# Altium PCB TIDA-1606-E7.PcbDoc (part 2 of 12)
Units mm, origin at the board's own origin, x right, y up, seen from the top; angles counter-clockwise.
Board outline 270 x 345 mm, 4 copper layers (Top Layer, Signal Layer 1, Signal Layer 2, Bottom Layer), stack 2.326 mm thick; 1282 components, 576 nets, 3628 pads, 4132 vias.
Unrouted connection lines stored in the file: 1719.
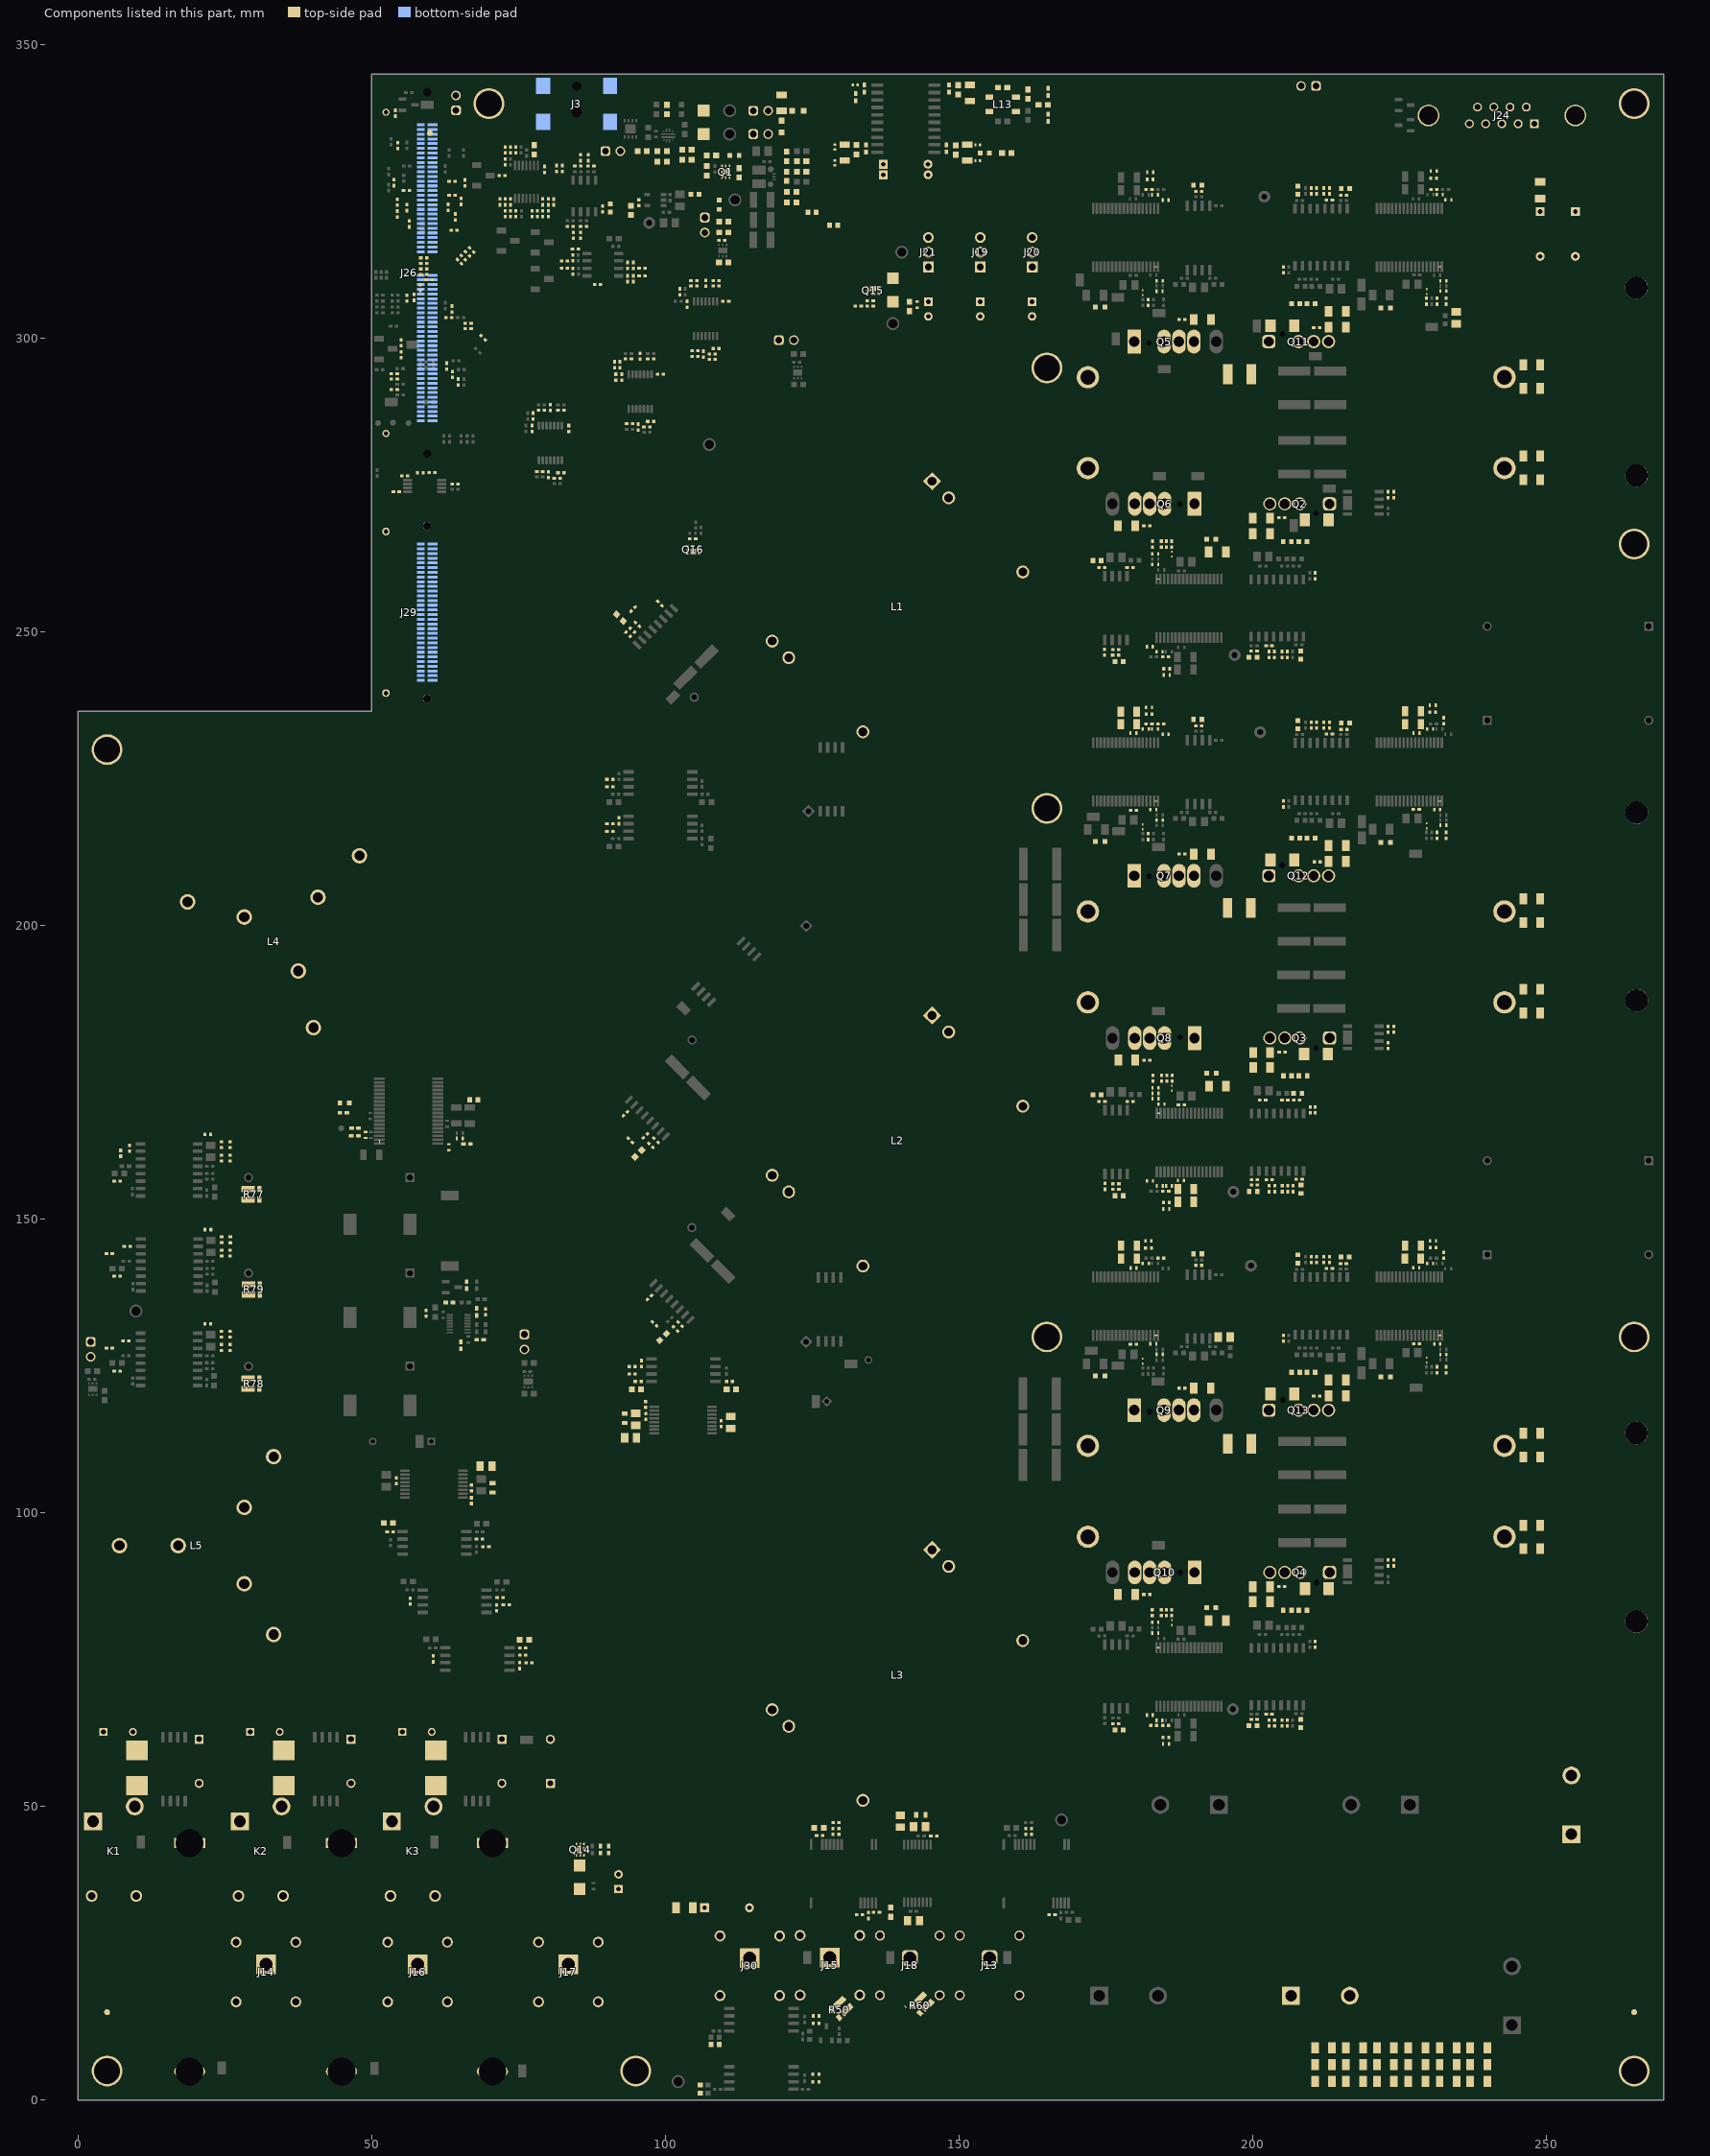
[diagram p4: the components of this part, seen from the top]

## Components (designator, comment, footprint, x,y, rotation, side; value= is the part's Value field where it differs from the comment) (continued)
C301 "GRM1555C1H101JA01D" 0402L 63.727,324.376 r0 top value=100pF
C302 "GRM155R71E104KE14D" 0402L 71.326,83.866 r270 top value=0.1uF
C303 "GRM155R71E104KE14D" 0402L 174.851,246.6 r270 top value=0.1uF
C304 "GCM155R71H104KE02D" 0402L 179.159,261.029 r180 top value=0.1uF
C305 "EMK107BB7225KA-T" 0603 52.884,98.3 r180 top value=2.2uF
C306 "GRM1555C1H101JA01D" 0402L 176.719,247.035 r0 top value=100pF
C307 "GCM155R71H104KE02D" 0402L 174.357,261.029 r180 top value=0.1uF
C308 "GRM155R71E104KE14D" 0402L 53.184,96.83 r0 top value=0.1uF
C309 "EMK107BB7225KA-T" 0603L 173.533,262.198 r0 top value=2.2uF
C310 "GRM1555C1E301JA01D" 0402L 79.511,328.803 r90 top value=300pF
C311 "EMK107BB7225KA-T" 0603 77.734,332.13 r90 top value=2.2uF
C312 "GRM155R71E104KE14D" 0402L 95.288,251.328 r135 top value=0.1uF
C313 "GRM1555C1E751JA01D" 0402L 72.759,323.261 r270 top value=750pF
C314 "GRM155R71E104KE14D" 0402L 95.532,323.12 r270 top value=0.1uF
C315 "GRM155R71E104KE14D" 0402L 223.117,179.6 r270 top value=0.1uF
C316 "GRM1555C1E751JA01D" 0402L 77.362,321.253 r90 top value=750pF
C317 "GRM155R71E104KE14D" 0402L 54.457,332.867 r90 top value=0.1uF
C318 "GRM155R71E104KE14D" 0402L 174.893,155.634 r270 top value=0.1uF
C319 "CL31B106KBHNNNE" 1206_180L 188.657,155.145 r0 top value=10uF
C320 "CL31B106KBHNNNE" 1206_180L 188.66,153 r0 top value=10uF
C321 "GCM155R71H104KE02D" 0402S 187.835,156.642 r0 top value=0.1uF
C322 "GRM155R71E104KE14D" 0402L 75.76,77.056 r180 top value=0.1uF
C323 "EMK107BB7225KA-T" 0603 76.06,78.425 r0 top value=2.2uF
C324 "CGA2B2C0G1H102J050BA" 0402L 56.637,85 r270 top value=1000pF
C325 "GCM155R71H104KE02D" 0402L 187.902,169.5 r0 top value=0.1uF
C326 "GRM1555C1H101JA01D" 0402L 53.802,326.525 r90 top value=100pF
C327 "GRM155R71E104KE14D" 0402L 75.21,74.025 r270 top value=0.1uF
C328 "GRM155R71E104KE14D" 0402L 96.646,164.233 r225 top value=0.1uF
C329 "GRM1555C1E301JA01D" 0402L 63.036,322.342 r90 top value=300pF
C330 "GRM155R71E104KE14D" 0402S 185.808,155.68 r0 top value=0.1uF
C331 "CGA2B2X7R1H331K050BA" 0402S 184.508,169.632 r180 top value=330pF
C332 "CGA2B2X7R1H331K050BA" 0402S 183.492,171.459 r180 top value=330pF
C333 "GRM1555C1H101JA01D" 0402L 200.339,156.753 r180 top value=100pF
C334 "GCM155R71H104KE02D" 0402L 207.518,170.288 r0 top value=0.1uF
C335 "GRM1555C1E751JA01D" 0402L 79.187,323.261 r270 top value=750pF
C336 "EMK107BB7225KA-T" 0603L 207.734,171.484 r180 top value=2.2uF
C337 "GCM155R71H104KE02D" 0402L 201.755,170.288 r180 top value=0.1uF
C338 "GRM155R71E104KE14D" 0402L 207.959,156.853 r0 top value=0.1uF
C339 "GCM155R71H104KE02D" 0402L 205.531,170.292 r0 top value=0.1uF
C340 "GRM1555C1E301JA01D" 0402L 223.117,91.501 r90 top value=300pF
C341 "GRM1555C1H101JA01D" 0402L 206.911,155.232 r270 top value=100pF
C342 "GRM1555C1H102JA01D" 0402L 129.098,47.3 r0 top value=1000pF
C343 "GRM1555C1H101JA01D" 0402L 209.839,168.632 r270 top value=100pF
C344 "GRM1555C1E301JA01D" 0402L 223.117,273.4 r90 top value=300pF
C345 "GRM1555C1E301JA01D" 0402L 223.117,182.381 r90 top value=300pF
C346 "GRM21BZ71A226ME15L" 0805_HV 143.326,46.6 r180 top value=22uF
C347 "GCM155R71H104KE02D" 0402L 179.201,170.063 r180 top value=0.1uF
C348 "GRM1555C1H101JA01D" 0402L 65.278,323.342 r90 top value=100pF
C349 "GRM1555C1H101JA01D" 0402L 176.761,156.069 r0 top value=100pF
C350 "GCM155R71H104KE02D" 0402L 174.391,170.055 r180 top value=0.1uF
C351 "GRM155R71E104KE14D" 0402L 92.12,217.874 r90 top value=0.1uF
C352 "EMK107BB7225KA-T" 0603L 173.574,171.232 r0 top value=2.2uF
C353 "EMK107BB7225KA-T" 0603 111.276,121.065 r0 top value=2.2uF
C354 "GRM155R71E104KE14D" 0402L 110.976,122.41 r180 top value=0.1uF
C355 "GRM155R71E104KE14D" 0402L 95.43,122.412 r0 top value=0.1uF
C356 "EMK107BB7225KA-T" 0603 95.13,121.043 r180 top value=2.2uF
C357 "CGA2B2C0G1H102J050BA" 0402L 60.532,75.172 r270 top value=1000pF
C358 "GRM1555C1H101JA01D" 0402L 55.969,325.185 r180 top value=100pF
C359 "GRM155R71E104KE14D" 0402L 95.989,125.452 r90 top value=0.1uF
C360 "GRM21BZ71A226ME15L" 0805_HV 140.042,47.516 r270 top value=22uF
C361 "GRM21BZ71A226ME15L" 0805_HV 111.186,115.412 r90 top value=22uF
C362 "CGA2B3X7R1H153K050BB" 0402L 109.51,115.225 r90 top value=0.015uF
C363 "CGA2B3X7R1H153K050BB" 0402L 96.691,116.458 r270 top value=0.015uF
C364 "GRM21BZ71A226ME15L" 0805_HV 95,115.942 r270 top value=22uF
C365 "EEU-FM1E101" FM_630x1120 92.078,37.232 r90 bottom value=100uF
C366 "EEU-FM1E101" FM_630x1120 162.495,305.025 r270 bottom value=100uF
C367 "EEU-FM1E101" FM_630x1120 153.658,305.025 r270 bottom value=100uF
C368 "EEU-FM1E101" FM_630x1120 144.822,305.025 r270 bottom value=100uF
C369 "GCM155R71H104KE02D" 0402S 142.932,305.767 r270 top value=0.1uF
C370 "CL31B106KBHNNNE" 1206_180L 130.556,331.653 r270 top value=10uF
C371 "GCM188R71C105KA64J" 0603 132.598,332.171 r270 top value=1uF
C372 "GRM155R71H103KA88D" 0402 134.2,332.371 r270 top value=0.01uF
C373 "GRM155R71E104KE14D" 0402 133.949,342.554 r270 top value=0.1uF
C374 "GRM155R71E104KE14D" 0402 148.336,342.554 r270 top value=0.1uF
C375 "GCM188R71C105KA64J" 0603 149.9,342.354 r270 top value=1uF
C376 "CL31B106KBHNNNE" 1206_180L 151.892,341.82 r270 top value=10uF
C377 "C1005C0G1H680J050BA" 0402 165.218,342.013 r270 top value=68pF
C378 "C0603X472K5RACTU" 0603 164.376,339.8 r180 top value=4700pF
C379 "C1005C0G1H680J050BA" 0402 165.217,337.591 r270 top value=68pF
C380 "GRM155R71H103KA88D" 0402 147.907,332.395 r270 top value=0.01uF
C381 "GCM188R71C105KA64J" 0603 149.474,332.09 r270 top value=1uF
C382 "CL31B106KBHNNNE" 1206_180L 151.463,331.653 r270 top value=10uF
C383 "GRM155R71E104KE14D" 0402L 103.746,305.831 r90 top value=0.1uF
C384 "GRM155R71E104KE14D" 0402L 92.606,293.413 r90 top value=0.1uF
C385 "GRM155R71E104KE14D" 0402L 55.019,297.24 r270 top value=0.1uF
C386 "GRM1555C1H101JA01D" 0402L 64.802,292.6 r270 top value=100pF
C387 "GRM1555C1H101JA01D" 0402L 63.778,293.9 r270 top value=100pF
C388 "GRM1555C1H101JA01D" 0402L 62.84,295.3 r270 top value=100pF
C389 "GRM1555C1H101JA01D" 0402L 92.306,295.553 r90 top value=100pF
C390 "GRM1555C1H101JA01D" 0402L 53.902,293.976 r180 top value=100pF
C391 "GRM1555C1H101JA01D" 0402L 53.902,293.091 r180 top value=100pF
C392 "GRM1555C1H101JA01D" 0402L 53.902,291.3 r180 top value=100pF
C393 "GRM155R71E104KE14D" 0402L 60.337,277.148 r180 top value=0.1uF
C394 "GRM155R71E104KE14D" 0402L 104.705,265.888 r180 top value=0.1uF
C395 "ALA8DA241CD500" FP-ALA8DA241CD500_RADIAL-MFG 254.308,50.314 r90 bottom value=240µF
C396 "ALA8DA241CD500" FP-ALA8DA241CD500_RADIAL-MFG 211.575,17.802 r0 bottom value=240µF
C397 "CL31B106KBHNNNE" 1206_180L 178.956,234.309 r180 top value=10uF
C398 "CL31B106KBHNNNE" 1206_180L 178.956,236.451 r180 top value=10uF
C399 "GCM155R71H104KE02D" 0402S 179.723,232.809 r180 top value=0.1uF
C400 "GCM155R71H104KE02D" 0402L 179.747,219.653 r180 top value=0.1uF
C401 "EMK107BB7225KA-T" 0603 141.6,305.475 r270 top value=2.2uF
C402 "GRM155R71E104KE14D" 0402S 181.838,233.5 r180 top value=0.1uF
C403 "CGA2B2X7R1H331K050BA" 0402S 183.138,219.807 r0 top value=330pF
C404 "CGA2B2X7R1H331K050BA" 0402S 184.209,218.008 r0 top value=330pF
C405 "CL31B106KBHNNNE" 1206_180L 178.982,143.332 r180 top value=10uF
C406 "CL31B106KBHNNNE" 1206_180L 178.982,145.529 r180 top value=10uF
C407 "GCM155R71H104KE02D" 0402S 179.756,141.732 r180 top value=0.1uF
C408 "GCM155R71H104KE02D" 0402L 179.737,128.721 r180 top value=0.1uF
C409 "EMK107BB7225KA-T" 0603 126.198,46.387 r0 top value=2.2uF
C410 "GRM155R71E104KE14D" 0402S 181.838,142.505 r180 top value=0.1uF
C411 "CGA2B2X7R1H331K050BA" 0402S 183.138,128.812 r0 top value=330pF
C412 "CGA2B2X7R1H331K050BA" 0402S 184.209,127.013 r0 top value=330pF
C413 "CL31B106KBHNNNE" 1206_180L 227.334,236.529 r180 top value=10uF
C414 "CL31B106KBHNNNE" 1206_180L 227.33,234.309 r180 top value=10uF
C415 "GCM155R71H104KE02D" 0402S 227.931,232.802 r180 top value=0.1uF
C416 "GCM155R71H104KE02D" 0402L 227.9,219.823 r180 top value=0.1uF
C417 "GRM155R71E104KE14D" 0402L 134.925,306.4 r0 top value=0.1uF
C418 "GRM155R71E104KE14D" 0402S 230.254,233.5 r180 top value=0.1uF
C419 "CGA2B2X7R1H331K050BA" 0402S 231.467,219.781 r0 top value=330pF
C420 "CGA2B2X7R1H331K050BA" 0402S 232.506,217.127 r0 top value=330pF
C421 "CL31B106KBHNNNE" 1206_180L 227.32,143.325 r180 top value=10uF
C422 "CL31B106KBHNNNE" 1206_180L 227.333,145.529 r180 top value=10uF
C423 "GCM155R71H104KE02D" 0402S 227.902,141.763 r180 top value=0.1uF
C424 "GCM155R71H104KE02D" 0402L 227.97,128.844 r180 top value=0.1uF
C425 "GRM155R71E104KE14D" 0402L 102.554,132.154 r315 top value=0.1uF
C426 "GRM155R71E104KE14D" 0402S 230.254,142.505 r180 top value=0.1uF
C427 "CGA2B2X7R1H331K050BA" 0402S 231.467,128.786 r0 top value=330pF
C428 "CGA2B2X7R1H331K050BA" 0402S 232.506,126.994 r0 top value=330pF
C429 "GRM155R71E104KE14D" 0402L 94.446,249.632 r225 top value=0.1uF
C430 "GRM155R71E104KE14D" 0402L 98.454,163.482 r315 top value=0.1uF
C431 "GCM155R71H104KE02D" 0402S 230.87,328.524 r180 top value=0.1uF
C432 "GCM155R71H104KE02D" 0402S 230.708,237.541 r180 top value=0.1uF
C433 "GCM155R71H104KE02D" 0402S 230.749,146.329 r180 top value=0.1uF
C434 "GCM155R71H104KE02D" 0402S 182.59,328.303 r180 top value=0.1uF
C435 "GCM155R71H104KE02D" 0402S 182.397,237.2 r180 top value=0.1uF
C436 "GCM155R71H104KE02D" 0402S 182.296,146.355 r180 top value=0.1uF
C437 "GCM155R71H104KE02D" 0402S 185.3,60.706 r0 top value=0.1uF
C438 "GCM155R71H104KE02D" 0402S 185.411,242.697 r0 top value=0.1uF
C439 "GCM155R71H104KE02D" 0402S 185.336,151.79 r0 top value=0.1uF
C440 "C1608X7R1V105K080AC" 0603L 128.7,319.287 r0 top value=1uF
C441 "CL31B106KBHNNNE" 1206_180L 119.837,340.13 r90 top value=10uF
C442 "C1608X7R1V105K080AC" 0603L 125.04,321.485 r180 top value=1uF
C443 "GRM155R71E104KE14D" 0402L 126.299,45.1 r180 top value=0.1uF
C444 "CGA2B2C0G1H102J050BA" 0402L 93.597,310.184 r90 top value=1000pF
C445 "GRM21BZ71A226ME15L" 0805_HV 94.121,112.793 r0 top value=22uF
C446 "GRM21BZ71A226ME15L" 0805_HV 142.301,30.6 r0 top value=22uF
C447 "CGA2B3X7R1H153K050BB" 0402L 54.2,105.5 r270 top value=0.015uF
C448 "CGA2B3X7R1H153K050BB" 0402L 67.02,104.267 r90 top value=0.015uF
C449 "GRM21BZ71A226ME15L" 0805_HV 69.521,108 r180 top value=22uF
C450 "GRM155R71E104KE14D" 0402L 89.36,322.054 r90 top value=0.1uF
C451 "EMK107BB7225KA-T" 0603L 90.66,322.254 r90 top value=2.2uF
C452 "EMK107BB7225KA-T" 0603 109.993,318.06 r0 top value=2.2uF
C454 "GRM155R71H102KA01D" 0402L 134.599,31.456 r90 top value=1000pF
C455 "CGA2B2C0G1H102J050BA" 0402L 93.597,312.462 r90 top value=1000pF
C456 "EMK107BB7225KA-T" 0603 138.432,32.035 r270 top value=2.2uF
C457 "GRM155R71E104KE14D" 0402L 135.998,32 r0 top value=0.1uF
C458 "C1812W104KDRACTU" 1812_254 197.816,293.939 r180 top value=0.1uF
C459 "C1812W104KDRACTU" 1812_254 197.755,203.056 r180 top value=0.1uF
C460 "C1812W104KDRACTU" 1812_254 197.816,111.782 r180 top value=0.1uF
C461 "GRM1555C1H101JA01D" 0402L 105.093,297.895 r180 top value=100pF
C462 "GRM1555C1H101JA01D" 0402L 108.043,297.346 r0 top value=100pF
C463 "GRM1555C1H101JA01D" 0402L 108.693,308.945 r0 top value=100pF
C464 "GRM1555C1H101JA01D" 0402L 104.896,308.946 r180 top value=100pF
C465 "GRM1555C1H101JA01D" 0402L 93.952,285.478 r180 top value=100pF
C466 "GRM1555C1H101JA01D" 0402L 96.902,284.929 r0 top value=100pF
C467 "GRM1555C1H101JA01D" 0402L 97.552,296.528 r0 top value=100pF
C468 "GRM1555C1H101JA01D" 0402L 93.756,296.529 r180 top value=100pF
C469 "GRM155R71E104KE14D" 0402L 77.34,284.673 r90 top value=0.1uF
C470 "GRM1555C1H101JA01D" 0402L 77.502,286.8 r90 top value=100pF
C471 "GRM1555C1H101JA01D" 0402L 78.662,277.368 r180 top value=100pF
C472 "GRM1555C1H101JA01D" 0402L 81.612,276.188 r0 top value=100pF
C473 "GRM1555C1H101JA01D" 0402L 82.262,287.787 r0 top value=100pF
C474 "GRM1555C1H101JA01D" 0402L 78.937,287.772 r180 top value=100pF
C475 "GRM1555C1H101JA01D" 0402L 202.879,156.755 r0 top value=100pF
C476 "GRM1555C1H101JA01D" 0402L 213.11,323.609 r180 top value=100pF
C477 "GRM1555C1H101JA01D" 0402L 213.112,232.641 r180 top value=100pF
C478 "GRM1555C1H101JA01D" 0402L 213.112,141.645 r180 top value=100pF
C479 "GRM1555C1H101JA01D" 0402L 202.838,247.721 r0 top value=100pF
C480 "GRM1555C1H101JA01D" 0402L 202.84,65.76 r0 top value=100pF
C481 "GRM1555C1H101JA01D" 0402L 66.474,302.6 r180 top value=100pF
C483 "GRM155R71E104KE14D" 0402L 109.667,316.7 r0 top value=0.1uF
C484 "EMK107BB7225KA-T" 0603 109.967,312.942 r0 top value=2.2uF
C485 "GRM1555C1E301JA01D" 0402L 54.402,323.2 r270 top value=300pF
C486 "GRM1555C1E301JA01D" 0402L 63.727,326.8 r0 top value=300pF
C487 "GRM1555C1E301JA01D" 0402L 56.002,322.285 r270 top value=300pF
C488 "GRM1555C1E301JA01D" 0402L 65.902,326.5 r90 top value=300pF
C489 "GRM1555C1E301JA01D" 0402L 56.452,319.5 r270 top value=300pF
C490 "GRM1555C1E301JA01D" 0402L 54.402,321.2 r90 top value=300pF
C492 "GRM1555C1E301JA01D" 0402L 64.302,320.7 r90 top value=300pF
D1 "150060VS75000" WL-SMCW_GREEN 111.802,331.17 r180 top value=Green
D2 "B330A-13-F" SMA 106.564,336.8 r90 top value=30V
D3 "150060VS75000" WL-SMCW_GREEN 109.193,322.785 r90 top value=Green
D4 "150060VS75000" WL-SMCW_GREEN 45.435,169.816 r0 top value=Green
D5 "B160-13-F" SMA 85.446,37.982 r90 top value=60V
D6 "B160-13-F" SMA 138.8,308.28 r90 top value=60V
D7 "NSR0130P2T5G" SOD-923 186.276,81.334 r90 top value=30V
D8 "US1Q-TP" FP-US1Q-TP_SMA-MFG 210.961,87.122 r180 top
D10 "US1Q-TP" FP-US1Q-TP_SMA-MFG 205.098,302.157 r0 top
D11 "US1Q-TP" FP-US1Q-TP_SMA-MFG 205.098,211.201 r0 top
D12 "US1Q-TP" FP-US1Q-TP_SMA-MFG 205.098,120.269 r0 top
D14 "NSR0130P2T5G" SOD-923 186.274,263.298 r90 top value=30V
D15 "US1Q-TP" FP-US1Q-TP_SMA-MFG 210.948,269.113 r180 top
D16 "NSR0130P2T5G" SOD-923 186.316,172.332 r90 top value=30V
D17 "US1Q-TP" FP-US1Q-TP_SMA-MFG 210.827,178.151 r180 top
D18 "150060VS75000" WL-SMCW_GREEN 154.441,331.605 r180 top value=Green
D19 "NSR0130P2T5G" SOD-923 229.657,308.006 r270 top value=30V
D20 "NSR0130P2T5G" SOD-923 229.666,217.031 r270 top value=30V
D21 "NSR0130P2T5G" SOD-923 229.666,126.036 r270 top value=30V
D22 "150060VS75000" WL-SMCW_GREEN 222.698,305.168 r0 top value=Green
D23 "150060VS75000" WL-SMCW_GREEN 222.7,214.2 r0 top value=Green
D24 "150060VS75000" WL-SMCW_GREEN 222.7,123.205 r0 top value=Green
D25 "NSR0130P2T5G" SOD-923 181.328,307.811 r270 top value=30V
D26 "NSR0130P2T5G" SOD-923 181.33,216.843 r270 top value=30V
D27 "NSR0130P2T5G" SOD-923 181.33,125.848 r270 top value=30V
D28 "150060VS75000" WL-SMCW_GREEN 174.085,305.339 r0 top value=Green
D29 "150060VS75000" WL-SMCW_GREEN 174.087,214.371 r0 top value=Green
D30 "150060VS75000" WL-SMCW_GREEN 174.087,123.376 r0 top value=Green
D31 "150060VS75000" WL-SMCW_GREEN 193,83.876 r180 top value=Green
D32 "150060VS75000" WL-SMCW_GREEN 192.998,265.84 r180 top value=Green
D33 "150060VS75000" WL-SMCW_GREEN 193.039,174.874 r180 top value=Green
F1 "PF-HT1-20" FP-PF-HT1-20_PTH_FUSE_38MM0_10MM3-MFG 19.044,24.348 r270 bottom
F2 "PF-HT1-20" FP-PF-HT1-20_PTH_FUSE_38MM0_10MM3-MFG 44.908,24.348 r270 bottom
F3 "PF-HT1-20" FP-PF-HT1-20_PTH_FUSE_38MM0_10MM3-MFG 70.6,24.348 r270 bottom
FB1 "74269244182" FP-74269244182_0402-MFG 25.912,160.456 r270 top
FB2 "74269244182" FP-74269244182_0402-MFG 25.927,162.703 r90 top
FB3 "74269244182" FP-74269244182_0402-MFG 22.12,164.456 r180 top
FB4 "74269244182" FP-74269244182_0402-MFG 25.912,128.198 r270 top
FB5 "74269244182" FP-74269244182_0402-MFG 25.927,130.445 r90 top
FB6 "74269244182" FP-74269244182_0402-MFG 22.12,132.198 r180 top
FB7 "74269244182" FP-74269244182_0402-MFG 25.954,144.271 r270 top
FB8 "74269244182" FP-74269244182_0402-MFG 25.969,146.518 r90 top
FB9 "74269244182" FP-74269244182_0402-MFG 22.162,148.271 r180 top
FB10 "74269244182" FP-74269244182_0402-MFG 230.878,327.304 r180 top
FB11 "74269244182" FP-74269244182_0402-MFG 230.716,236.372 r180 top
FB12 "74269244182" FP-74269244182_0402-MFG 230.757,145.205 r180 top
FB13 "74269244182" FP-74269244182_0402-MFG 182.598,327.1 r180 top
FB14 "74269244182" FP-74269244182_0402-MFG 182.404,236.042 r180 top
FB15 "74269244182" FP-74269244182_0402-MFG 182.297,145.11 r180 top
FB16 "BLM15EX331SN1D" FP-BLM15EX331SN1D_0402-MFG 128.88,332.603 r90 top
FB17 "BLM15EX331SN1D" FP-BLM15EX331SN1D_0402-MFG 132.389,343.154 r0 top
FB18 "BLM15EX331SN1D" FP-BLM15EX331SN1D_0402-MFG 153.241,332.971 r0 top
FB19 "BLM15EX331SN1D" FP-BLM15EX331SN1D_0402-MFG 153.241,330.271 r0 top
FB20 "BLM15EX331SN1D" FP-BLM15EX331SN1D_0402-MFG 128.88,329.903 r90 top
FB21 "74269244182" FP-74269244182_0402-MFG 185.297,61.788 r0 top
FB22 "74269244182" FP-74269244182_0402-MFG 185.403,243.764 r0 top
FB23 "74269244182" FP-74269244182_0402-MFG 185.328,152.857 r0 top
FB24 "LCMGA160808T601RG" FP-LCMGA160808T601RG_0603-MFG 122.615,338.78 r0 top
FB25 "LCMGA160808T601RG" FP-LCMGA160808T601RG_0603-MFG 119.837,336.1 r270 top
FID1 "Fiducial" Fiducial10-20#1 5,15 r0 top
FID2 "Fiducial" Fiducial10-20#2 60,335 r0 top
FID3 "Fiducial" Fiducial10-20#1 265,15 r0 top
J1 "61300211121" WURTH_61300211121 91.102,331.9 r0 top
J2 "61300211121" WURTH_61300211121 116.272,338.8 r0 top
J3 "PJ-002AH-SMT-TR" CUI_PJ-002AH-SMT 84.948,339.947 r270 bottom
J4 "999-11-113-10-000000" Mill-Max_999-11-113-10-000000 254.988,317.81 r270 top
J5 "999-11-113-10-000000" Mill-Max_999-11-113-10-000000 249,317.81 r270 top
J6 "999-11-113-10-000000" Mill-Max_999-11-113-10-000000 110.548,32.788 r0 top
J8 "61300211121" WURTH_61300211121 116.272,334.813 r0 top
J10 "61300211121" WURTH_61300211121 120.65,299.72 r0 top
J11 "61300211121" WURTH_61300211121 2.2,127.87 r270 top
J12 "61300211121" WURTH_61300211121 76.04,129.142 r270 top
J13 "FCR7350R" Cliff_FCR7350R 155.243,24.249 r180 bottom locked
J14 "FCR7350N" FP-FCR7350N_CONN_BANANA_JACK-MFG 32.04,12.13 r90 bottom
J15 "FCR7350Y" FP-FCR7350Y_CONN_BANANA_JACK-MFG 128.065,13.274 r90 bottom locked
J16 "FCR7350N" FP-FCR7350N_CONN_BANANA_JACK-MFG 57.854,12.13 r90 bottom
J17 "FCR7350N" FP-FCR7350N_CONN_BANANA_JACK-MFG 83.533,12.13 r90 bottom
J18 "FCR7350B" Cliff_FCR7350B 141.669,24.249 r180 bottom locked
J19 "0022111031" FP-0022111031_HDR3-MFG 153.962,314.7 r270 bottom
J20 "0022111031" FP-0022111031_HDR3-MFG 162.795,314.7 r270 bottom
J21 "0022111031" FP-0022111031_HDR3-MFG 145.129,314.7 r270 bottom
J22 "999-11-113-10-000000" Mill-Max_999-11-113-10-000000 140.97,327.893 r0 top
J23 "999-11-113-10-000000" Mill-Max_999-11-113-10-000000 140.952,329.688 r0 top
J24 "618009231121" Wurth_618009231121 242.488,347.488 r90 bottom
J25 "61300211121" WURTH_61300211121 209.55,342.997 r180 top
J26 "HSEC8-160-01-L-RA-BL" Samtec_HSEC8-160-01-x-RA-BL 59.477,311.185 r0 bottom locked
J27 "61300211121" WURTH_61300211121 64.402,340.119 r90 top
J29 "HSEC8-130-01-L-RA" FP-HSEC8-130-01-L-RA_HDR60-MFG 56.202,253.385 r90 bottom locked
J30 "FCR7350G" FP-FCR7350G_CONN_BANANA_JACK-MFG 114.426,13.185 r90 bottom locked
J31 "61300211121" WURTH_61300211121 106.767,319.33 r270 top
K1 "2071556-3" FP-2071556-3_PTH_RELAY_18MM2_10MM2-MFG 6.15,42.727 r270 bottom
K2 "2071556-3" FP-2071556-3_PTH_RELAY_18MM2_10MM2-MFG 31.149,42.727 r270 bottom
K3 "2071556-3" FP-2071556-3_PTH_RELAY_18MM2_10MM2-MFG 57.035,42.727 r270 bottom
L1 "B181108 D6665 V2" "FP-B181108 D6665 V2_PTH_IND_52MM5_59MM0-MFG" 140.983,252.95 r225 bottom locked value=160uH
L2 "B181108 D6665 V2" "FP-B181108 D6665 V2_PTH_IND_52MM5_59MM0-MFG" 140.985,161.981 r225 bottom locked value=160uH
L3 "B181108 D6665 V2" "FP-B181108 D6665 V2_PTH_IND_52MM5_59MM0-MFG" 140.983,70.986 r225 bottom locked value=160uH
L4 "WK 3260A" "FP-WK 3260A_PTH6_41MM5_43MM5-MFG" 35.597,199.548 r135 bottom
L5 "WK 3260A" "FP-WK 3260A_PTH6_41MM5_43MM5-MFG" 24.6,94.452 r270 bottom
L6 "782763102" 1206 103.283,32.8 r0 top value="1000 ohm"
L7 "74279228260" 0603L 106,1.9 r90 top value="26 ohm"
L8 "74279228260" 0603L 108.537,9.5 r0 top value="26 ohm"
L9 "782763102" 1206 249,325.255 r270 top value="1000 ohm"
L11 "74479763222" WE-PMI_0603_L1.6W0.8H0.8 143.542,48.6 r180 top
L12 "74479763222" WE-PMI_0603_L1.6W0.8H0.8 93.1,116.158 r270 top
L13 "ACT45B-101-2P-TL003" FP-ACT45B-101-2P-TL003_SMT_4MM5_3MM2-MFG 157.48,339.888 r0 top
L14 "74479763222" WE-PMI_0603_L1.6W0.8H0.8 70.605,104.31 r90 top
LBL1 "THT-14-423-10" Label_650x200 227.341,27.015 r0 top
Logo1 "CE Mark" CE_Mark_5mm 209.764,27.224 r0 top
LOGO2 "CAUTION HOT SURFACE" IEC_HotSurface_Medium 212.128,243.738 r180 bottom
Logo3 "FCC disclaimer" FCC_disclaimer 188.376,-25.388 r90 top
Logo4 "WEEE logo" WEEE_Minimum 197.906,27.478 r0 top
LOGO5 "DANGER HIGH VOLTAGE" IEC_HighVoltage_Medium 147.677,76.361 r0 top
LOGO6 "CAUTION HOT SURFACE" IEC_HotSurface_Medium 134.163,76.666 r0 top
LOGO7 "DANGER HIGH VOLTAGE" IEC_HighVoltage_Medium 147.677,255.78 r0 top
LOGO8 "DANGER HIGH VOLTAGE" IEC_HighVoltage_Medium 147.677,165.039 r0 top
LOGO9 "CAUTION HOT SURFACE" IEC_HotSurface_Medium 134.163,165.344 r0 top
LOGO10 "CAUTION HOT SURFACE" IEC_HotSurface_Medium 134.163,256.084 r0 top
LOGO11 "CAUTION HOT SURFACE" IEC_HotSurface_Medium 212.128,152.404 r180 bottom
LOGO12 "DANGER HIGH VOLTAGE" IEC_HighVoltage_Medium 224.215,243.434 r180 bottom
LOGO13 "DANGER HIGH VOLTAGE" IEC_HighVoltage_Medium 224.215,152.099 r180 bottom
MP1 "C247-075-3AE" FP-C247-075-3AE_PTH_HTSNK_75MM0_18MM0-MFG 207.452,183.962 r180 bottom locked
MP2 "C247-075-3AE" FP-C247-075-3AE_PTH_HTSNK_75MM0_18MM0-MFG 207.452,114.436 r0 bottom locked
MP3 "C247-075-3AE" FP-C247-075-3AE_PTH_HTSNK_75MM0_18MM0-MFG 207.452,92.966 r180 bottom locked
MP4 "C247-075-3AE" FP-C247-075-3AE_PTH_HTSNK_75MM0_18MM0-MFG 207.451,205.426 r0 bottom locked
MP5 "C247-075-3AE" FP-C247-075-3AE_PTH_HTSNK_75MM0_18MM0-MFG 207.45,296.4 r0 bottom locked
MP6 "C247-075-3AE" FP-C247-075-3AE_PTH_HTSNK_75MM0_18MM0-MFG 207.45,274.93 r180 bottom locked
MP7 "9774040960R" FP-9774040960R_ROUND_SPACER_6MM0-MFG 265,5 r0 top
MP8 "9774040960R" FP-9774040960R_ROUND_SPACER_6MM0-MFG 265,130 r0 top
MP9 "9774040960R" FP-9774040960R_ROUND_SPACER_6MM0-MFG 265,265 r0 top
MP10 "9774040960R" FP-9774040960R_ROUND_SPACER_6MM0-MFG 265,340 r0 top
MP11 "9774040960R" FP-9774040960R_ROUND_SPACER_6MM0-MFG 95,5 r0 top
MP12 "9774040960R" FP-9774040960R_ROUND_SPACER_6MM0-MFG 165,130 r0 top
MP13 "9774040960R" FP-9774040960R_ROUND_SPACER_6MM0-MFG 165,220 r0 top
MP14 "9774040960R" FP-9774040960R_ROUND_SPACER_6MM0-MFG 165,295 r0 top
MP15 "9774040960R" FP-9774040960R_ROUND_SPACER_6MM0-MFG 5,5 r0 top
MP16 "9774040960R" FP-9774040960R_ROUND_SPACER_6MM0-MFG 70,340 r0 top
MP17 "9774040960R" FP-9774040960R_ROUND_SPACER_6MM0-MFG 5,230 r0 top
MP18 "613" FP-613_MNT_BRACKET-MFG 264.395,276.671 r0 bottom
MP19 "613" FP-613_MNT_BRACKET-MFG 264.395,308.671 r0 bottom
MP20 "613" FP-613_MNT_BRACKET-MFG 264.395,81.557 r0 bottom
MP21 "613" FP-613_MNT_BRACKET-MFG 264.395,113.63 r0 bottom
MP22 "613" FP-613_MNT_BRACKET-MFG 264.441,187.293 r0 bottom
MP23 "613" FP-613_MNT_BRACKET-MFG 264.441,219.293 r0 bottom
MP24 "DC0401012V2B-3T3" FP-DC0401012V2B_FAN-MFG 253.981,292.755 r180 bottom
MP25 "DC0401012V2B-3T3" FP-DC0401012V2B_FAN-MFG 254.027,203.291 r180 bottom
MP26 "DC0401012V2B-3T3" FP-DC0401012V2B_FAN-MFG 253.981,97.601 r180 bottom
NT9 "Net-Tie" Net-Tie7milsWide_20milsLong 140.91,15.937 r315 top net-tie
NT17 "Net-Tie" Net-Tie7milsWide_20milsLong 51.343,163.255 r90 top net-tie
NT18 "Net-Tie" Net-Tie7milsWide_20milsLong 183.96,77.074 r0 top net-tie
NT19 "Net-Tie" Net-Tie7milsWide_20milsLong 231.951,312.218 r180 top net-tie
NT20 "Net-Tie" Net-Tie7milsWide_20milsLong 183.589,312.208 r180 top net-tie
NT21 "Net-Tie" Net-Tie7milsWide_20milsLong 183.994,259.035 r0 top net-tie
NT22 "Net-Tie" Net-Tie7milsWide_20milsLong 184.057,168.069 r0 top net-tie
NT23 "Net-Tie" Net-Tie7milsWide_20milsLong 183.595,221.247 r180 top net-tie
NT24 "Net-Tie" Net-Tie7milsWide_20milsLong 183.595,130.251 r180 top net-tie
NT25 "Net-Tie" Net-Tie7milsWide_20milsLong 231.884,221.19 r180 top net-tie
NT26 "Net-Tie" Net-Tie7milsWide_20milsLong 231.941,130.251 r180 top net-tie
Q1 "CSD17571Q2" DQK0006C 110.329,328.395 r270 top value=30V
Q2 "C3M0075120K" TO-247-4 208.057,271.85 r180 bottom value=1200V
Q3 "C3M0075120K" TO-247-4 208.059,180.882 r180 bottom value=1200V
Q4 "C3M0075120K" TO-247-4 208.059,89.887 r180 bottom value=1200V
Q5 "C3M0060065K" FP-C3M0060065K_TO-247-4L-MFG 184.963,299.267 r270 bottom
Q6 "C3M0060065K" FP-C3M0060065K_TO-247-4L-MFG 185.053,272.063 r90 bottom
Q7 "C3M0060065K" FP-C3M0060065K_TO-247-4L-MFG 184.965,208.299 r270 bottom
Q8 "C3M0060065K" FP-C3M0060065K_TO-247-4L-MFG 185.055,181.094 r90 bottom
Q9 "C3M0060065K" FP-C3M0060065K_TO-247-4L-MFG 184.965,117.303 r270 bottom
Q10 "C3M0060065K" FP-C3M0060065K_TO-247-4L-MFG 185.055,90.099 r90 bottom
Q11 "C3M0075120K" TO-247-4 207.891,299.48 r0 bottom value=1200V
Q12 "C3M0075120K" TO-247-4 207.893,208.511 r0 bottom value=1200V
Q13 "C3M0075120K" TO-247-4 207.893,117.516 r0 bottom value=1200V
Q14 "CSD17571Q2" DQK0006C 85.552,42.7 r90 top value=30V
Q15 "CSD17571Q2" DQK0006C 135.4,308.175 r0 top value=30V
Q16 "CSD17318Q2" FP-CSD17318Q2_WSON6-MFG 104.8,264.043 r180 top
R1 "RC0603FR-07470KL" 0603 96.102,331.9 r180 top value=470k
R2 "RC0603FR-0747KL" 0603 103.725,332.147 r0 top value=47.0k
R3 "RC0603FR-071K1L" 0603 100.29,339 r270 top value=1.10k
R4 "RC0603FR-075K6L" 0603 103.725,330.448 r180 top value=5.60k
R5 "RC0603FR-0711KL" 0603 99.49,331.9 r180 top value=11.0k
R6 "RC0603FR-0747KL" 0603 107.885,331.17 r0 top value=47.0k
R7 "RC0603FR-072KL" 0603 112.602,328.22 r90 top value=2.00k
R8 "RC0603FR-0747KL" 0603 99.506,330.1 r0 top value=47.0k
R9 "RC0603FR-0715KL" 0603 107.076,328.57 r90 top value=15.0k
R10 "ERJ-2RKF49R9X" 0402L 66.351,314.418 r135 top value=49.9
R11 "RC0603FR-0754K9L" 0603 120.702,331.004 r90 top value=54.9k
R12 "RC0603FR-07220KL" 0603 123.245,328.417 r0 top value=220k
R13 "RC0603FR-0730KL" 0603 120.702,327.617 r90 top value=30.0k
R14 "RG1608P-103-B-T5" 0603 123.245,330.171 r0 top value=10.0k
R15 "CRCW0603499RFKEAC" 0603 109.993,319.902 r180 top value=499
R16 "RC0603FR-0730KL" 0603 121.537,323.184 r0 top value=30.0k
R17 "RC0603JR-070RL" 0603 94.16,321.82 r90 top value=0
R18 "RC0603FR-0747KL" 0603 121.537,324.977 r180 top value=47.0k
R19 "ERA-2AEB153X" 0402L 84.27,311.462 r270 top value=15.0k
R20 "ERJ-2RKF1000X" 0402L 161.4,45.789 r90 top value=100
R21 "RC0402JR-070RL" 0402L 165.9,31.582 r180 top value=0
R22 "MCS0402MD1002BE100" 0402L 82.87,311.962 r180 top value=10.0k
R23 "CRCW040230K0FKED" 0402L 145.742,45 r0 top value=30.0k
R24 "CRCW0402309RFKED" 0402L 84.726,315.275 r180 top value=309
R25 "MCS0402MD1002BE100" 0402L 82.87,313.226 r180 top value=10.0k
R26 "ERJ-2RKF1000X" 0402L 162.4,45.789 r90 top value=100
R27 "ERJ-2RKF1000X" 0402L 128.598,45.789 r90 top value=100
R28 "ERA-2AEB153X" 0402L 84.27,313.724 r90 top value=15.0k
R29 "ERA-2AEB153X" 0402L 94.57,310.184 r270 top value=15.0k
R30 "ERJ-2RKF1000X" 0402L 129.598,45.789 r90 top value=100
R31 "RC0402JR-070RL" 0402L 133.098,31.582 r180 top value=0
R32 "MCS0402MD1002BE100" 0402L 96.07,310.687 r0 top value=10.0k
R33 "CRCW0402309RFKED" 0402L 88.502,309.189 r180 top value=309
R34 "MCS0402MD1002BE100" 0402L 96.07,311.962 r0 top value=10.0k
R35 "RCS06030000Z0EA" 0603L 105.091,324.559 r0 top value=0
R36 "RCS06030000Z0EA" 0603L 67.421,170.359 r0 top value=0
R37 "ERA-2AEB153X" 0402L 94.57,312.464 r90 top value=15.0k
R38 "ERJ-2GEJ102X" 0402 47.209,165.521 r180 top value=1.0k
R39 "CRCW040238K3FKED" 0402 47.174,164.221 r180 top value=38.3k
R40 "MCS0402MD1002BE100" 0402S 49.011,164.363 r90 top value=10.0k
R41 "CRCW1206510KJNEA" 1206 212.097,3.192 r180 top value=510k
R42 "CRCW1206510KJNEA" 1206 212.097,8.928 r180 top value=510k
R43 "CRCW1206510KJNEA" 1206 212.097,6.06 r180 top value=510k
R44 "CRCW1206510KJNEA" 1206 217.371,3.192 r180 top value=510k
R45 "CRCW1206510KJNEA" 1206 217.371,8.928 r180 top value=510k
R46 "CRCW1206510KJNEA" 1206 217.371,6.06 r180 top value=510k
R47 "CRCW1206510KJNEA" 1206 222.64,3.192 r180 top value=510k
R48 "CRCW1206510KJNEA" 1206 222.64,8.928 r180 top value=510k
R49 "CRCW1206510KJNEA" 1206 222.64,6.06 r180 top value=510k
R50 "WSKW06122L000FEA" FP-WSKW06122L000FEA_0612-MFG 129.932,15.656 r135 top value=2m
R51 "CRCW1206510KJNEA" 1206 227.992,3.192 r180 top value=510k
R52 "CRCW1206510KJNEA" 1206 227.992,8.928 r180 top value=510k
R53 "CRCW1206510KJNEA" 1206 227.992,6.06 r180 top value=510k
R54 "CRCW1206510KJNEA" 1206 233.326,3.192 r180 top value=510k
R55 "CRCW1206510KJNEA" 1206 233.326,8.928 r180 top value=510k
R56 "CRCW1206510KJNEA" 1206 233.326,6.06 r180 top value=510k
R57 "CRCW1206510KJNEA" 1206 238.542,3.192 r180 top value=510k
R58 "CRCW1206510KJNEA" 1206 238.542,8.928 r180 top value=510k
R59 "CRCW1206510KJNEA" 1206 238.542,6.06 r180 top value=510k
R60 "WSKW06122L000FEA" FP-WSKW06122L000FEA_0612-MFG 143.714,16.409 r135 top value=2m
R61 "ERJ-2RKF2001X" 0402 45.235,168.163 r180 top value=2.00k
R62 "ERJ-2RKF49R9X" 0402L 67.053,315.089 r135 top value=49.9
R63 "ERJ-2RKF1000X" 0402L 90.6,223.669 r180 top value=100
R64 "ERJ-2RKF6980X" 0402 66.214,138.801 r90 top value=698
R65 "ERJ-2RKF1000X" 0402L 90.6,224.939 r180 top value=100
R66 "ERJ-2RKF49R9X" 0402L 69.418,134.263 r90 top value=49.9
R67 "CRCW0402200RJNED" 0402 63.249,135.846 r180 top value=200
R68 "ERJ-2RKF1000X" 0402L 90.6,216.104 r180 top value=100
R69 "ERJ-2RKF1001X" 0402 67.913,134.263 r90 top value=1.00k
R70 "ERJ-2RKF1000X" 0402L 90.6,217.374 r180 top value=100
R71 "RC0402JR-070RL" 0402L 59.333,133.993 r90 top value=0
R72 "ERJ-2RKF1501X" 0402 68.513,129.515 r180 top value=1.50k
R73 "ERJ-2RKF1000X" 0402L 94.38,123.682 r180 top value=100
R74 "CRCW040210K0FKED" 0402 65.246,128.567 r90 top value=10.0k
R75 "ERJ-2RKF1000X" 0402L 94.38,124.943 r180 top value=100
R76 "CRCW040230K0FKED" 0402L 96.68,118.5 r90 top value=30.0k
R77 "WSKW06122L000FEA" FP-WSKW06122L000FEA_0612-MFG 29.598,154.269 r270 top value=2m
R78 "WSKW06122L000FEA" FP-WSKW06122L000FEA_0612-MFG 29.598,122.011 r270 top value=2m
R79 "WSKW06122L000FEA" FP-WSKW06122L000FEA_0612-MFG 29.64,138.084 r270 top value=2m
R80 "CRCW040210K0FKED" 0402L 205.012,87.51 r180 top value=10.0k
R81 "CRCW040210K0FKED" 0402L 182.015,86.136 r180 top value=10.0k
R82 "CRCW040210K0FKED" 0402L 210.938,301.856 r0 top value=10.0k
R83 "CRCW040210K0FKED" 0402L 211.04,210.888 r0 top value=10.0k
R84 "CRCW040210K0FKED" 0402L 210.938,119.9 r0 top value=10.0k
R85 "CRCW040210K0FKED" 0402L 188.003,303.23 r0 top value=10.0k
R86 "CRCW040210K0FKED" 0402L 188.005,212.262 r0 top value=10.0k
R87 "CRCW040210K0FKED" 0402L 188.005,121.266 r0 top value=10.0k
R88 "CRCW040210K0FKED" 0402L 205.01,269.474 r180 top value=10.0k
R89 "PTCEL13R600LBE" FP-PTCEL13R600LBE_RADIAL-MFG 6.875,62.729 r0 bottom value=60O
R90 "UPR25J4R7CT" FP-UPR25J4R7CT_2512-MFG 10.058,56.591 r270 top value=4.7
R91 "PTCEL13R600LBE" FP-PTCEL13R600LBE_RADIAL-MFG 31.874,62.729 r0 bottom value=60O
R92 "UPR25J4R7CT" FP-UPR25J4R7CT_2512-MFG 35.052,56.591 r270 top value=4.7
R93 "CRCW040210K0FKED" 0402L 182.013,268.1 r180 top value=10.0k
R94 "PTCEL13R600LBE" FP-PTCEL13R600LBE_RADIAL-MFG 57.76,62.729 r0 bottom value=60O
R95 "UPR25J4R7CT" FP-UPR25J4R7CT_2512-MFG 60.96,56.591 r270 top value=4.7
R96 "IsoM5-275-B-L2" FP-IsoM5-275-B-L2_RADIAL-MFG 20.659,57.729 r270 bottom
R97 "IsoM5-275-B-L2" FP-IsoM5-275-B-L2_RADIAL-MFG 46.523,57.729 r270 bottom
R98 "IsoM5-275-B-L2" FP-IsoM5-275-B-L2_RADIAL-MFG 72.215,57.729 r270 bottom
R99 "CRCW040210K0FKED" 0402L 205.052,178.508 r180 top value=10.0k
R100 "IsoM5-275-B-L2" FP-IsoM5-275-B-L2_RADIAL-MFG 80.468,57.729 r90 bottom
R101 "ERJ-2RKF33R0X" 0402L 106.546,297.346 r270 top value=33.0
R102 "ERJ-2RKF33R0X" 0402L 108.693,298.296 r0 top value=33.0
R103 "ERJ-2RKF33R0X" 0402L 110.346,306.331 r0 top value=33.0
R104 "ERJ-2GEJ104X" 0402S 63.181,162.306 r90 top value=100k
R105 "ERJ-2RKF33R0X" 0402L 106.893,309.393 r90 top value=33.0
R106 "ERJ-2RKF33R0X" 0402L 95.406,284.929 r270 top value=33.0
R107 "ERJ-2RKF33R0X" 0402L 97.552,285.879 r0 top value=33.0
R108 "ERJ-2RKF33R0X" 0402L 99.206,293.913 r0 top value=33.0
R109 "CRCW040230K0FKED" 0402 66.254,162.857 r0 top value=30.0k
R110 "ERJ-2RKF33R0X" 0402L 95.752,296.976 r90 top value=33.0
R111 "MCS0402MD1002BE100" 0402S 65.024,163.802 r180 top value=10.0k
R112 "ERJ-2RKF33R0X" 0402L 80.115,276.82 r270 top value=33.0
R113 "CRCW0402200RJNED" 0402 90.4,42.7 r270 top value=200
R114 "ERJ-2RKF33R0X" 0402L 82.262,277.138 r0 top value=33.0
R115 "CRCW040210K0FKED" 0402 89.014,42.7 r270 top value=10.0k
R116 "ERJ-2RKF33R0X" 0402L 83.601,284.673 r270 top value=33.0
R117 "RC1206FR-072R7L" 1206 247.574,185.166 r180 top value=2.70
R118 "RC1206FR-072R7L" 1206 247.574,113.566 r180 top value=2.70
R119 "RC1206FR-072R7L" 1206 247.574,97.917 r180 top value=2.70
R120 "RC1206FR-072R7L" 1206 247.574,189.205 r180 top value=2.70
R121 "RC1206FR-072R7L" 1206 247.574,109.55 r180 top value=2.70
R122 "RC1206FR-072R7L" 1206 247.574,93.929 r180 top value=2.70
R123 "RC1206FR-072R7L" 1206 247.574,204.572 r180 top value=2.70
R124 "RC1206FR-072R7L" 1206 247.574,295.504 r180 top value=2.70
R125 "RC1206FR-072R7L" 1206 247.574,279.984 r180 top value=2.70
R126 "RC1206FR-072R7L" 1206 247.574,200.558 r180 top value=2.70
R127 "RC1206FR-072R7L" 1206 247.574,291.49 r180 top value=2.70
R128 "RC1206FR-072R7L" 1206 247.574,275.946 r180 top value=2.70
R129 "CRCW040210K0FKED" 0402L 54.107,338.362 r90 top value=10.0k
R130 "CRCW0402200RJNED" 0402L 132.9,305.5 r0 top value=200
R131 "CRCW040210K0FKED" 0402L 134.925,305.5 r180 top value=10.0k
R132 "RC0402FR-0747KL" 0402L 6.7,156.534 r180 top value=47.0k
R133 "ERJ-2RKF49R9X" 0402L 8.8,162.1 r90 top value=49.9
R134 "CPF0402B10RE1" CPF0402 24.456,160.456 r90 top value=10.0
R135 "ERJ-2RKF49R9X" 0402L 8.2,129.342 r180 top value=49.9
R136 "CPF0402B10RE1" CPF0402 24.456,162.713 r270 top value=10.0
R137 "RC0402FR-0747KL" 0402L 6.7,124.2 r180 top value=47.0k
R138 "ERJ-2RKF49R9X" 0402L 8.415,145.415 r180 top value=49.9
R139 "CPF0402B10RE1" CPF0402 24.456,128.198 r90 top value=10.0
R140 "RC0402JR-070RL" 0402L 7.3,161.256 r90 top value=0
R141 "CPF0402B10RE1" CPF0402 24.456,130.455 r270 top value=10.0
R142 "RC0402FR-0747KL" 0402L 6.7,140.35 r180 top value=47.0k
R143 "RC0402JR-070RL" 0402L 5.381,128.068 r180 top value=0
R144 "CPF0402B10RE1" CPF0402 24.498,144.271 r90 top value=10.0
R145 "RC0402JR-070RL" 0402L 5.381,144.147 r180 top value=0
R146 "CPF0402B10RE1" CPF0402 24.498,146.528 r270 top value=10.0
R147 "CRCW04022K00FKED" 0402L 185.385,83.034 r270 top value=2.00k
R148 "ERJ-2GEJ104X" 0402S 182.53,65.574 r180 top value=100k
R149 "CRCW0402392RFKED" 0402L 186.276,83.034 r90 top value=392
R150 "CRCW040266K5FKED" 0402L 182.945,83.034 r90 top value=66.5k
R151 "CRCW040230K0FKED" 0402L 184.494,83.034 r90 top value=30.0k
R152 "MCS0402MD1002BE100" 0402S 184.175,64.685 r0 top value=10.0k
R153 "CRCW040230K0FKED" 0402L 185.219,63.836 r0 top value=30.0k
R154 "CRCW04022K00FKED" 0402L 185.383,264.998 r270 top value=2.00k
R155 "MCS0402MD1002BE100" 0402S 183.452,79.572 r0 top value=10.0k
R156 "PCF0402-03-49K9BT1" 0402S 183.453,81.4 r0 top value=49.9k
R157 "RCS06030000Z0EA" 0603L 200.1,63.778 r180 top value=0
R158 "CRCW040210K0FKED" 0402L 200.3,64.836 r0 top value=10.0k
R159 "CRCW040210K0FKED" 0402L 202.822,64.236 r270 top value=10.0k
R160 "CRCW040210K0FKED" 0402L 203.772,64.236 r270 top value=10.0k
R161 "CRCW040210K0FKED" 0402L 205.958,64.236 r270 top value=10.0k
R162 "RC0603JR-070RL" 0603L 208.23,64.136 r270 top value=0
R163 "ERJ-3EKF1472V" 0603L 205.944,83.452 r180 top value=14.7k
R164 "CRCW12060000Z0EA" 1206 201.534,87.445 r0 top value=0
R165 "CRCW12060000Z0EA" 1206 201.534,84.905 r0 top value=0
R166 "RC0603FR-0711KL" 0603L 208.584,83.452 r180 top value=11.0k
R167 "ERJ-2RKF1000X" 0402L 205.044,64.236 r90 top value=100
R168 "ERJ-2RKF33R0X" 0402L 80.462,288.235 r90 top value=33.0
R169 "CRCW04022K00FKED" 0402L 210.666,77.634 r90 top value=2.00k
R170 "CRCW040220R0FKED" 0402L 64.237,275.228 r0 top value=20.0
R171 "ERJ-2RKF1000X" 0402L 68.39,95.56 r0 top value=100
R172 "ERJ-8RQF3R3V" 1206 178.58,86.136 r0 top value=3.30
R173 "CRCW040266K5FKED" 0402L 182.99,264.998 r90 top value=66.5k
R174 "RCS06030000Z0EA" 0603L 177.295,63.047 r0 top value=0
R175 "CRCW040210K0FKED" 0402L 176.721,64.145 r0 top value=10.0k
R176 "MCS0402MD1002BE100" 0402L 78.251,321.253 r270 top value=10.0k
R177 "CRCW040210K0FKED" 0402L 98.195,132.218 r135 top value=10.0k
R178 "CRCW040210K0FKED" 0402L 97.339,136.701 r45 top value=10.0k
R179 "MCS0402MD1002BE100" 0402L 79.187,321.253 r270 top value=10.0k
R180 "CRCW0402309RFKED" 0402L 81.039,323.25 r270 top value=309
R181 "MCS0402MD1002BE100" 0402L 80.111,321.253 r270 top value=10.0k
R182 "CRCW040210K0FKED" 0402L 224.1,91.501 r270 top value=10.0k
R183 "RC0603FR-0747K5L" 0603 99.649,129.977 r45 top value=47.5k
R184 "MCS0402MD1002BE100" 0402L 80.111,323.261 r270 top value=10.0k
R185 "CRCW040210K0FKED" 0402L 101.768,131.368 r315 top value=10.0k
R186 "ERJ-2RKF2490X" 0402L 229.664,306.366 r270 top value=249
R187 "ERJ-2GEJ104X" 0402S 233.365,323.605 r0 top value=100k
R188 "CRCW040230K0FKED" 0402L 230.888,325.405 r180 top value=30.0k
R189 "ERJ-6GEYJ391V" 0805_HV 234.7,303.516 r270 top value=390
R190 "CRCW040266K5FKED" 0402L 233.002,306.366 r270 top value=66.5k
R191 "CRCW040230K0FKED" 0402L 231.455,306.366 r270 top value=30.0k
R192 "CRCW040220R0FKED" 0402L 54.237,273.928 r180 top value=20.0
R193 "MCS0402MD1002BE100" 0402S 231.896,324.505 r180 top value=10.0k
R194 "MCS0402MD1002BE100" 0402S 232.504,309.803 r180 top value=10.0k
R195 "PCF0402-03-49K9BT1" 0402S 232.504,308.095 r180 top value=49.9k
R196 "RCS06030000Z0EA" 0603L 215.829,325.518 r0 top value=0
R197 "CRCW040210K0FKED" 0402L 215.529,324.397 r180 top value=10.0k
R198 "CRCW040210K0FKED" 0402L 213.128,325.132 r90 top value=10.0k
R199 "CRCW040210K0FKED" 0402L 212.178,325.132 r90 top value=10.0k
R200 "CRCW040210K0FKED" 0402L 209.992,325.132 r90 top value=10.0k
R201 "RC0603JR-070RL" 0603L 207.72,325.232 r90 top value=0
R202 "ERJ-3EKF1472V" 0603L 210.006,305.914 r0 top value=14.7k
R203 "CRCW12060000Z0EA" 1206 214.422,301.93 r180 top value=0
R204 "CRCW12060000Z0EA" 1206 214.422,304.622 r180 top value=0
R205 "RC0603FR-0711KL" 0603L 207.366,305.914 r0 top value=11.0k
R206 "ERJ-2RKF1000X" 0402L 210.906,325.132 r270 top value=100
R207 "ERJ-2RKF1000X" 0402L 69.5,94.3 r0 top value=100
R208 "CRCW04022K00FKED" 0402L 205.284,311.708 r270 top value=2.00k
R209 "CRCW040220R0FKED" 0402L 55.651,276.6 r180 top value=20.0
R210 "RCS06030000Z0EA" 0603L 215.831,234.55 r0 top value=0
R211 "RCS06030000Z0EA" 0603L 215.795,143.6 r0 top value=0
R212 "CRCW040210K0FKED" 0402L 215.595,233.429 r180 top value=10.0k
R213 "CRCW040210K0FKED" 0402L 213.13,234.164 r90 top value=10.0k
R214 "CRCW040210K0FKED" 0402L 212.18,234.164 r90 top value=10.0k
R215 "CRCW040210K0FKED" 0402L 209.994,234.164 r90 top value=10.0k
R216 "RC0603JR-070RL" 0603L 207.722,234.264 r90 top value=0
R217 "ERJ-3EKF1472V" 0603L 210.008,214.945 r0 top value=14.7k
R218 "CRCW12060000Z0EA" 1206 214.423,210.964 r180 top value=0
R219 "CRCW12060000Z0EA" 1206 214.423,213.676 r180 top value=0
R220 "RC0603FR-0711KL" 0603L 207.368,214.945 r0 top value=11.0k
R221 "ERJ-2RKF1000X" 0402L 210.908,234.164 r270 top value=100
R222 "ERJ-2RKF1000X" 0402L 71.901,85.626 r0 top value=100
R223 "CRCW04022K00FKED" 0402L 205.286,220.74 r270 top value=2.00k
R224 "RCS06030000Z0EA" 0603L 190.675,326.11 r180 top value=0
R225 "ERJ-2RKF1000X" 0402L 72.956,84.356 r0 top value=100
R226 "RCS06030000Z0EA" 0603L 190.677,235.142 r180 top value=0
R227 "CRCW040210K0FKED" 0402L 215.495,142.433 r180 top value=10.0k
R228 "CRCW040210K0FKED" 0402L 213.13,143.169 r90 top value=10.0k
R229 "CRCW040210K0FKED" 0402L 212.18,143.169 r90 top value=10.0k
R230 "CRCW040210K0FKED" 0402L 209.994,143.169 r90 top value=10.0k
R231 "RC0603JR-070RL" 0603L 207.722,143.269 r90 top value=0
R232 "ERJ-3EKF1472V" 0603L 210.008,123.95 r0 top value=14.7k
R233 "CRCW12060000Z0EA" 1206 214.423,119.965 r180 top value=0
R234 "ERA-2AEB752X" 0402L 85.125,329.386 r180 top value=7.50k
R235 "CRCW12060000Z0EA" 1206 214.423,122.669 r180 top value=0
R236 "RC0603FR-0711KL" 0603L 207.368,123.95 r0 top value=11.0k
R237 "ERJ-2RKF1000X" 0402L 210.908,143.169 r270 top value=100
R238 "CPF0402B10RE1" CPF0402 125.676,3.119 r180 top value=10.0
R239 "MCS0402MD1002BE100" 0402L 85.625,330.786 r90 top value=10.0k
R240 "CRCW0402309RFKED" 0402L 82.502,328.967 r90 top value=309
R241 "MCS0402MD1002BE100" 0402L 86.889,330.786 r90 top value=10.0k
R242 "RCS06030000Z0EA" 0603L 190.677,144.147 r180 top value=0
R243 "CPF0402B10RE1" CPF0402 125.676,4.427 r180 top value=10.0
R244 "ERA-2AEB752X" 0402L 87.387,329.386 r180 top value=7.50k
R245 "CRCW04022K00FKED" 0402L 205.286,129.744 r270 top value=2.00k
R246 "RCS06030000Z0EA" 0603L 200.098,245.739 r180 top value=0
R247 "CRCW040230K0FKED" 0402L 67.02,102.11 r270 top value=30.0k
R248 "CRCW04022K00FKED" 0402L 182.242,306.146 r90 top value=2.00k
R249 "ERJ-2GEJ104X" 0402S 185.223,323.598 r0 top value=100k
R250 "CRCW040230K0FKED" 0402L 182.397,325.368 r180 top value=30.0k
R251 "ERJ-2RKF1000X" 0402L 75.76,75.786 r0 top value=100
R252 "CRCW040266K5FKED" 0402L 233.004,215.398 r270 top value=66.5k
R253 "CRCW040230K0FKED" 0402L 231.457,215.398 r270 top value=30.0k
R254 "CRCW0805499RFKEA" 0805_HV 195.2,129.943 r0 top value=499
R255 "MCS0402MD1002BE100" 0402S 183.407,324.468 r180 top value=10.0k
R256 "MCS0402MD1002BE100" 0402S 184.207,309.818 r180 top value=10.0k
R257 "PCF0402-03-49K9BT1" 0402S 184.198,308.049 r180 top value=49.9k
R258 "ERJ-8RQF3R3V" 1206 191.493,303.23 r180 top value=3.30
R259 "CRCW040230K0FKED" 0402L 184.492,264.998 r90 top value=30.0k
R260 "RCS06030000Z0EA" 0603L 177.285,245 r0 top value=0
R261 "CRCW040210K0FKED" 0402L 190.875,325.039 r180 top value=10.0k
R262 "ERJ-8RQF3R3V" 1206 191.495,212.207 r180 top value=3.30
R263 "CRCW04022K00FKED" 0402L 182.244,215.178 r90 top value=2.00k
R264 "RCS06030000Z0EA" 0603L 200.139,154.773 r180 top value=0
R265 "CRCW040210K0FKED" 0402L 190.877,234.071 r180 top value=10.0k
R266 "ERJ-8RQF3R3V" 1206 191.457,121.266 r180 top value=3.30
R267 "ERJ-2GEJ104X" 0402S 185.225,232.63 r0 top value=100k
R268 "RCS06030000Z0EA" 0603L 177.327,154.034 r0 top value=0
R269 "CRCW040210K0FKED" 0402L 190.877,142.178 r180 top value=10.0k
R270 "ERA-2AEB752X" 0402L 83.847,319.086 r180 top value=7.50k
R271 "CPF0402B10RE1" CPF0402 125.718,13.09 r0 top value=10.0
R272 "MCS0402MD1002BE100" 0402L 84.347,317.589 r90 top value=10.0k
R273 "CRCW0402309RFKED" 0402L 81.502,328.967 r270 top value=309
R274 "MCS0402MD1002BE100" 0402L 85.614,317.589 r90 top value=10.0k
R275 "CPF0402B10RE1" CPF0402 125.718,14.36 r0 top value=10.0
R276 "ERA-2AEB752X" 0402L 86.114,319.086 r0 top value=7.50k
R277 "CRCW0402392RFKED" 0402L 186.274,264.998 r90 top value=392
R278 "ERJ-2GEJ104X" 0402S 182.528,247.536 r180 top value=100k
R279 "CRCW040230K0FKED" 0402L 185.217,245.798 r0 top value=30.0k
R280 "CRCW040230K0FKED" 0402L 182.399,234.4 r180 top value=30.0k
R281 "CRCW040266K5FKED" 0402L 233.004,124.402 r270 top value=66.5k
R282 "MCS0402MD1002BE100" 0402S 184.184,246.646 r0 top value=10.0k
R283 "CRCW04022K00FKED" 0402L 185.424,174.032 r270 top value=2.00k
R284 "CRCW0402392RFKED" 0402L 186.316,174.032 r90 top value=392
R285 "MCS0402MD1002BE100" 0402S 183.45,261.535 r0 top value=10.0k
R286 "PCF0402-03-49K9BT1" 0402S 183.451,263.334 r0 top value=49.9k
R287 "CPF0402B10RE1" CPF0402 58.337,277.148 r0 top value=10.0
R288 "CRCW040210K0FKED" 0402L 200.298,246.798 r0 top value=10.0k
R289 "CRCW040210K0FKED" 0402L 202.82,246.198 r270 top value=10.0k
R290 "CRCW040210K0FKED" 0402L 203.77,246.198 r270 top value=10.0k
R291 "CRCW040210K0FKED" 0402L 205.956,246.198 r270 top value=10.0k
R292 "RC0603JR-070RL" 0603L 208.228,246.098 r270 top value=0
R293 "ERJ-3EKF1472V" 0603L 205.942,265.416 r180 top value=14.7k
R294 "CRCW12060000Z0EA" 1206 201.527,269.423 r0 top value=0
R295 "CRCW12060000Z0EA" 1206 201.527,266.749 r0 top value=0
R296 "RC0603FR-0711KL" 0603L 208.582,265.416 r180 top value=11.0k
R297 "ERJ-2RKF1000X" 0402L 205.042,246.198 r90 top value=100
R298 "CRCW04022K00FKED" 0402L 210.664,259.598 r90 top value=2.00k
R299 "ERJ-2GEJ104X" 0402L 66.474,301.7 r0 top value=100k
R300 "ERJ-2RKF1000X" 0402L 76.81,74.525 r0 top value=100
R301 "CRCW040210K0FKED" 0402L 224.09,273.4 r270 top value=10.0k
R302 "CRCW040230K0FKED" 0402L 231.457,124.402 r270 top value=30.0k
R303 "ERJ-8RQF3R3V" 1206 178.578,268.1 r0 top value=3.30
R304 "RC0402JR-070RL" 0402L 64.068,318.4 r180 top value=0
R305 "CRCW040210K0FKED" 0402L 176.706,246.093 r0 top value=10.0k
R306 "MCS0402MD1002BE100" 0402L 74.586,332.105 r90 top value=10.0k
R307 "CRCW040210K0FKED" 0402L 94.554,253.919 r45 top value=10.0k
R308 "CRCW040210K0FKED" 0402L 99.112,254.854 r315 top value=10.0k
R309 "MCS0402MD1002BE100" 0402L 73.674,332.1 r90 top value=10.0k
R310 "CRCW0402309RFKED" 0402L 72.259,327.775 r180 top value=309
R311 "MCS0402MD1002BE100" 0402L 72.761,332.1 r90 top value=10.0k
R312 "RC0603FR-0747K5L" 0603 92.313,252.466 r315 top value=47.5k
R313 "MCS0402MD1002BE100" 0402L 72.761,330.06 r90 top value=10.0k
R314 "CRCW040210K0FKED" 0402L 93.704,250.346 r225 top value=10.0k
R315 "CRCW040210K0FKED" 0402L 224.09,182.381 r270 top value=10.0k
R316 "CRCW040230K0FKED" 0402L 185.258,154.832 r0 top value=30.0k
R317 "ERJ-2GEJ104X" 0402S 182.57,156.57 r180 top value=100k
R318 "CRCW12062K00JNEA" 1206 194,81.684 r0 top value=2.0k
R319 "CRCW040266K5FKED" 0402L 183.031,174.032 r90 top value=66.5k
R320 "CRCW040230K0FKED" 0402L 184.533,174.032 r90 top value=30.0k
R321 "MCS0402MD1002BE100" 0402S 184.234,155.68 r0 top value=10.0k
R322 "CRCW12062K00JNEA" 1206 193.998,263.648 r0 top value=2.0k
R323 "CRCW12062K00JNEA" 1206 194.039,172.682 r0 top value=2.0k
R324 "MCS0402MD1002BE100" 0402S 183.492,170.569 r0 top value=10.0k
R325 "PCF0402-03-49K9BT1" 0402S 183.494,172.405 r0 top value=49.9k
R326 "ERJ-2RKF49R9X" 0402L 65.639,313.763 r135 top value=49.9
R327 "CRCW040210K0FKED" 0402L 200.339,155.832 r0 top value=10.0k
R328 "CRCW040210K0FKED" 0402L 202.861,155.232 r270 top value=10.0k
R329 "CRCW040210K0FKED" 0402L 203.811,155.232 r270 top value=10.0k
R330 "CRCW040210K0FKED" 0402L 205.997,155.232 r270 top value=10.0k
R331 "RC0603JR-070RL" 0603L 208.269,155.132 r270 top value=0
R332 "ERJ-3EKF1472V" 0603L 205.983,174.45 r180 top value=14.7k
R333 "CRCW12060000Z0EA" 1206 201.569,178.419 r0 top value=0
R334 "CRCW12060000Z0EA" 1206 201.569,175.879 r0 top value=0
R335 "RC0603FR-0711KL" 0603L 208.623,174.45 r180 top value=11.0k
R336 "ERJ-2RKF1000X" 0402L 205.083,155.232 r90 top value=100
R337 "CRCW040210K0FKED" 0402L 176.761,155.14 r0 top value=10.0k
R338 "CRCW04022K00FKED" 0402L 210.705,168.632 r90 top value=2.00k
R339 "CRCW040210K0FKED" 0402L 94.079,163.46 r135 top value=10.0k
R340 "CRCW040210K0FKED" 0402L 93.246,168.003 r45 top value=10.0k
R341 "ERJ-8RQF3R3V" 1206 178.62,177.134 r0 top value=3.30
R342 "MCS0402MD1002BE100" 0402S 183.409,233.5 r180 top value=10.0k
R343 "ERJ-2RKF49R9X" 0402L 58.902,310.918 r0 top value=49.9
R344 "CRCW040210K0FKED" 0402L 97.582,162.61 r315 top value=10.0k
R345 "MCS0402MD1002BE100" 0402L 74.6,321.253 r270 top value=10.0k
R346 "MCS0402MD1002BE100" 0402L 73.674,321.253 r270 top value=10.0k
R347 "CRCW0402309RFKED" 0402L 71.868,323.261 r270 top value=309
R348 "MCS0402MD1002BE100" 0402L 72.761,321.253 r270 top value=10.0k
R349 "MCS0402MD1002BE100" 0402L 73.674,323.261 r270 top value=10.0k
R350 "CRCW040210K0FKED" 0402L 182.055,177.134 r180 top value=10.0k
R351 "RC0402JR-070RL" 0402L 232.548,234.928 r270 top value=0
R352 "RC0603FR-0747K5L" 0603 95.463,161.219 r45 top value=47.5k
R353 "RC0402JR-070RL" 0402L 232.548,143.896 r270 top value=0
R354 "ERJ-2RKF49R9X" 0402L 64.981,313.098 r135 top value=49.9
R355 "ERJ-2RKF49R9X" 0402L 63.686,305.018 r90 top value=49.9
R356 "ERJ-2RKF49R9X" 0402L 58.902,311.858 r0 top value=49.9
R357 "ERJ-2RKF49R9X" 0402L 58.902,312.797 r0 top value=49.9
R358 "ERJ-2RKF49R9X" 0402L 58.902,313.737 r0 top value=49.9
R359 "RC0402JR-070RL" 0402L 69.006,300.146 r135 top value=0
R360 "ERJ-2RKF49R9X" 0402L 56.002,306.868 r270 top value=49.9
R361 "RC0402JR-070RL" 0402L 184.424,234.4 r180 top value=0
R362 "ERJ-2RKF49R9X" 0402L 59.802,309.985 r0 top value=49.9
R363 "RC0402JR-070RL" 0402L 184.424,143.405 r180 top value=0
R364 "RC0402JR-070RL" 0402L 183.203,63.836 r0 top value=0
R365 "ERJ-2RKF49R9X" 0402L 58.302,308.685 r270 top value=49.9
R366 "ERJ-2RKF49R9X" 0402L 57.241,307 r270 top value=49.9
R367 "ERJ-2RKF49R9X" 0402L 63.186,303.6 r180 top value=49.9
R374 "CRCW04023K30JNED" 0402L 55.019,299.289 r90 top value=3.3k
R375 "CRCW040210K0FKED" 0402L 102.546,307.971 r270 top value=10.0k
R376 "CRCW040210K0FKED" 0402L 105.093,296.946 r0 top value=10.0k
R377 "CRCW040210K0FKED" 0402L 108.046,296.446 r180 top value=10.0k
R378 "CRCW040210K0FKED" 0402L 104.896,309.882 r0 top value=10.0k
R379 "CRCW040210K0FKED" 0402L 108.693,309.865 r180 top value=10.0k
R380 "CRCW040210R0JNED" 0402L 91.606,293.413 r270 top value=10
R381 "CRCW040210K0FKED" 0402L 91.406,295.553 r270 top value=10.0k
R382 "CRCW0603499RFKEAC" 0603 158.179,331.585 r180 top value=499
R383 "CRCW040210K0FKED" 0402 132.438,341.121 r90 top value=10.0k
R384 "RCS06030000Z0EA" 0603 157.48,342.738 r180 top value=0
R385 "RT0603DRE0759R7L" 0603 161.798,341.612 r90 top value=59.7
